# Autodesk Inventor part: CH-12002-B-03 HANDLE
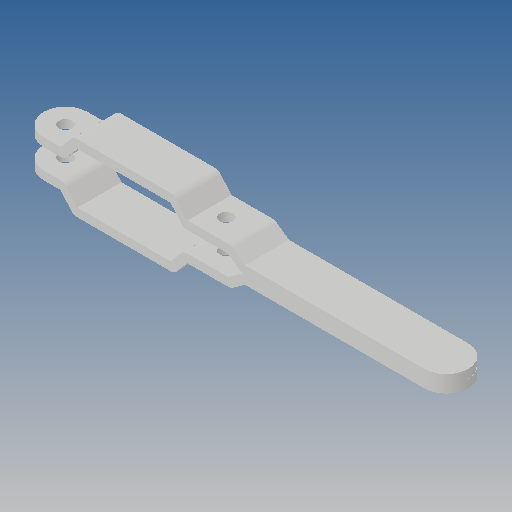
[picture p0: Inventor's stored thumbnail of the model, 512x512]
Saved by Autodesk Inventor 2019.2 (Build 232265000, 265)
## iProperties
Created: 2012-09
Part Number: CH-12002-B-03 HANDLE
Material: Ogólny
Document SubType Name: Modeling
Designer: CADENGINEERING4
Density: 1 g/cm^3
Appearance: Domyślna
Author: CADENGINEERING4
Revision Number: ÈÎºÎ
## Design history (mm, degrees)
feature "ÇÐ³ý-À­Éì1"
feature "¾µÏò1"
node "Bryła1"
node "Bryła2"
